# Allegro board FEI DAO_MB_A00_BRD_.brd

Outline 331.5 x 112.9 mm; copper layers: TOP, GND1, IN1, VCC, IN2, IN3, GND2, IN4, GND3, BOTTOM. Coordinates in mm from the lower left corner of the outline.

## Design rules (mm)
net group 5_10: nets PCH_SDVO_CTRLCLK PCH_SDVO_CTRLDATA
net group CARD_SMBCLK: nets CARD_SMBCLK CARD_SMBDAT
net group CLK_BUF_CKSSCD: nets CLK_BUF_CKSSCD CLK_BUF_CKSSCD#
net group CLK_BUF_DMI: nets CLK_BUF_DMI CLK_BUF_DMI#
net group CLK_BUF_DOT96: nets CLK_BUF_DOT96 CLK_BUF_DOT96#
net group CSS_1: nets CSSN_1 CSSP_1
net group DIFFPAIR0: nets HOST_DEBUG_RX HOST_DEBUG_TX
net group DMI_CRX_PTX_0: nets DMI_CRX_PTX_N0 DMI_CRX_PTX_P0
net group DMI_CRX_PTX_1: nets DMI_CRX_PTX_N1 DMI_CRX_PTX_P1
net group DMI_CRX_PTX_2: nets DMI_CRX_PTX_N2 DMI_CRX_PTX_P2
net group DMI_CRX_PTX_3: nets DMI_CRX_PTX_N3 DMI_CRX_PTX_P3
net group DMI_CTX_PRX_0: nets DMI_CTX_PRX_N0 DMI_CTX_PRX_P0
net group DMI_CTX_PRX_1: nets DMI_CTX_PRX_N1 DMI_CTX_PRX_P1
net group DMI_CTX_PRX_2: nets DMI_CTX_PRX_N2 DMI_CTX_PRX_P2
net group DMI_CTX_PRX_3: nets DMI_CTX_PRX_N3 DMI_CTX_PRX_P3
net group DMIC_CLK: nets DMIC0 DMIC_CLK
net group ESATA_PRX_DTX_P4_RP: nets ESATA_PRX_DTX_N4_RP ESATA_PRX_DTX_P4_RP
net group FDI_CTX_PRX_0: nets FDI_CTX_PRX_N0 FDI_CTX_PRX_P0
net group FDI_CTX_PRX_1: nets FDI_CTX_PRX_N1 FDI_CTX_PRX_P1
net group FDI_CTX_PRX_2: nets FDI_CTX_PRX_N2 FDI_CTX_PRX_P2
net group FDI_CTX_PRX_3: nets FDI_CTX_PRX_N3 FDI_CTX_PRX_P3
net group FDI_CTX_PRX_4: nets FDI_CTX_PRX_N4 FDI_CTX_PRX_P4
net group FDI_CTX_PRX_5: nets FDI_CTX_PRX_N5 FDI_CTX_PRX_P5
net group FDI_CTX_PRX_6: nets FDI_CTX_PRX_N6 FDI_CTX_PRX_P6
net group FDI_CTX_PRX_7: nets FDI_CTX_PRX_N7 FDI_CTX_PRX_P7
net group GND: nets GND GNDA
net group GPU_SMBCLK: nets GPU_SMBCLK GPU_SMBDAT
net group LCD_SMBCLK: nets LCD_SMBCLK LCD_SMBDAT
net group LDDC_DATA_PCH: nets LDDC_CLK_PCH LDDC_DATA_PCH
net group M_CLK_DDR0: nets M_CLK_DDR0 M_CLK_DDR#0
net group M_CLK_DDR1: nets M_CLK_DDR1 M_CLK_DDR#1
net group M_CLK_DDR2: nets M_CLK_DDR2 M_CLK_DDR#2
net group M_CLK_DDR3: nets M_CLK_DDR3 M_CLK_DDR#3
net group MSCLK: nets MSCLK MSDATA
net group NB_LAN_TX0: nets NB_LAN_TX0+ NB_LAN_TX0-
net group NB_LAN_TX1: nets NB_LAN_TX1+ NB_LAN_TX1-
net group NB_LAN_TX2: nets NB_LAN_TX2+ NB_LAN_TX2-
net group NB_LAN_TX3: nets NB_LAN_TX3+ NB_LAN_TX3-
net group PCH_CL_CLK1: nets PCH_CL_CLK1 PCH_CL_DATA1
net group PCH_CRT_DDC_CLK: nets PCH_CRT_DDC_CLK PCH_CRT_DDC_DAT
net group PCH_SDVO_CRTLCLK_R: nets PCH_SDVO_CTRLCLK_R PCH_SDVO_CTRLDATA_R
net group REM_DIODE1_4022: nets REM_DIODE1_N_4022 REM_DIODE1_P_4022
net group REM_DIODE2_4022: nets REM_DIODE2_N_4022 REM_DIODE2_P_4022
net group SATA_PRX_DTX_P4_B: nets SATA_PRX_DTX_N4_B SATA_PRX_DTX_P4_B
net group SATA_PTX_DRX_P4_B: nets SATA_PTX_DRX_N4_B SATA_PTX_DRX_P4_B
net group TMDSB_CON_CLK: nets TMDSB_CON_CLK TMDSB_CON_CLK#
net group TMDSB_PCH_CLK: nets TMDSB_PCH_CLK TMDSB_PCH_CLK#
net group TMDSB_PCH_CLK_C: nets TMDSB_PCH_CLK#_C TMDSB_PCH_CLK_C
net group TP_CLK: nets TP_CLK TP_DATA
net group UIM: nets UIM_CLK UIM_DATA
net group USB3RN1_D: nets USB3RN1_D- USB3RP1_D+
net group USB3RN2_D: nets USB3RN2_D- USB3RP2_D+
net group USB3RN3_D: nets USB3RN3_D- USB3RP3_D+
net group USB3TN1_D: nets USB3TN1_D- USB3TP1_D+
net group USB3TP2_D: nets USB3TN2_D- USB3TP2_D+
net group USB3TP3_D: nets USB3TN3_D- USB3TP3_D+
net group USBP13: nets USBP13+ USBP13-
net group USBP13_R_D: nets USBP13_R_D+ USBP13_R_D-
net group USH_SMBCLK: nets USH_SMBCLK USH_SMBDAT
net group ASYNCHRONOUS: nets EDP_COMP PEG_COMP SATA3_COMP SATA_COMP
net group AUDIO: nets AUD_HP_OUT_L AUD_HP_OUT_L1 AUD_HP_OUT_L2 AUD_HP_OUT_R AUD_HP_OUT_R1 AUD_HP_OUT_R2 EXT_MIC INT_SPK_L+ INT_SPK_L- INT_SPK_R+ INT_SPK_R- INT_SPKL_L+ INT_SPKR_L- INT_SPKR_R+ INT_SPKR_R- ME_FWP MIC_IN_L MIC_IN_R PCH_AZ_BITCLK PCH_AZ_CODEC_BITCLK PCH_AZ_CODEC_RST# PCH_AZ_CODEC_SDIN0 PCH_AZ_CODEC_SDOUT PCH_AZ_CODEC_SYNC PCH_AZ_RST# PCH_AZ_SDIN0_R PCH_AZ_SDOUT PCH_AZ_SYNC PCH_AZ_SYNC_Q
net group CARD READER: nets SD/MMCCD# SD/MMCDAT0 SD/MMCDAT0_R SD/MMCDAT1 SD/MMCDAT1_R SD/MMCDAT2 SD/MMCDAT2_R SD/MMCDAT3 SD/MMCDAT3_R SD/MMCDAT4 SD/MMCDAT4_R SD/MMCDAT5 SD/MMCDAT5_R SD/MMCDAT6 SD/MMCDAT6_R SD/MMCDAT7 SD/MMCDAT7_R
net group CPU SIDEBAND: nets DDR3_DRAMRST# DDR3_DRAMRST#_CPU DDR3_DRAMRST#_R H_CPUPWRGD H_CPUPWRGD_XDP H_PM_SYNC H_PROCHOT# H_PROCHOT#_R H_THERMTRIP# H_THERMTRIP#_R PCH_PLTRST# PCH_PLTRST#_BUF PCH_PLTRST#_EC PCH_PLTRST#_R PM_DRAM_PWRGD PM_DRAM_PWRGD_CPU PROCHOT#_EC RUNPWROK_AND THERMATRIP2# VCCPWRGOOD_0_R XDP_RST#_R
net group CRT: nets B G HSYNC HSYNC_BUF HSYNC_CRT JVGA_HS JVGA_VS R VSYNC VSYNC_BUF VSYNC_CRT
net group CRT_20: nets BLUE_CRT GREEN_CRT RED_CRT
net group DDR_A_CMD: nets DDR_A_BS0 DDR_A_BS1 DDR_A_BS2 DDR_A_CAS# DDR_A_MA0 DDR_A_MA1 DDR_A_MA2 DDR_A_MA3 DDR_A_MA4 DDR_A_MA5 DDR_A_MA6 DDR_A_MA7 DDR_A_MA8 DDR_A_MA9 DDR_A_MA10 DDR_A_MA11 DDR_A_MA12 DDR_A_MA13 DDR_A_MA14 DDR_A_MA15 DDR_A_RAS# DDR_A_WE#
net group DDR_A_CTL: nets DDR_CKE0_DIMMA DDR_CKE1_DIMMA DDR_CS0_DIMMA# DDR_CS1_DIMMA#
net group DDR_A_D0: nets DDR_A_D0 DDR_A_D1 DDR_A_D2 DDR_A_D3 DDR_A_D4 DDR_A_D5 DDR_A_D6 DDR_A_D7
net group DDR_A_D1: nets DDR_A_D8 DDR_A_D9 DDR_A_D10 DDR_A_D11 DDR_A_D12 DDR_A_D13 DDR_A_D14 DDR_A_D15
net group DDR_A_D2: nets DDR_A_D16 DDR_A_D17 DDR_A_D18 DDR_A_D19 DDR_A_D20 DDR_A_D21 DDR_A_D22 DDR_A_D23
net group DDR_A_D3: nets DDR_A_D24 DDR_A_D25 DDR_A_D26 DDR_A_D27 DDR_A_D28 DDR_A_D29 DDR_A_D30 DDR_A_D31
net group DDR_A_D4: nets DDR_A_D32 DDR_A_D33 DDR_A_D34 DDR_A_D35 DDR_A_D36 DDR_A_D37 DDR_A_D38 DDR_A_D39
net group DDR_A_D5: nets DDR_A_D40 DDR_A_D41 DDR_A_D42 DDR_A_D43 DDR_A_D44 DDR_A_D45 DDR_A_D46 DDR_A_D47
net group DDR_A_D6: nets DDR_A_D48 DDR_A_D49 DDR_A_D50 DDR_A_D51 DDR_A_D52 DDR_A_D53 DDR_A_D54 DDR_A_D55
net group DDR_A_D7: nets DDR_A_D56 DDR_A_D57 DDR_A_D58 DDR_A_D59 DDR_A_D60 DDR_A_D61 DDR_A_D62 DDR_A_D63
net group DDR_A_DQS: nets DDR_A_DQS0 DDR_A_DQS1 DDR_A_DQS2 DDR_A_DQS3 DDR_A_DQS4 DDR_A_DQS5 DDR_A_DQS6 DDR_A_DQS7 DDR_A_DQS#0 DDR_A_DQS#1 DDR_A_DQS#2 DDR_A_DQS#3 DDR_A_DQS#4 DDR_A_DQS#5 DDR_A_DQS#6 DDR_A_DQS#7
net group DDR_B_CMD: nets DDR_B_BS0 DDR_B_BS1 DDR_B_BS2 DDR_B_CAS# DDR_B_MA0 DDR_B_MA1 DDR_B_MA2 DDR_B_MA3 DDR_B_MA4 DDR_B_MA5 DDR_B_MA6 DDR_B_MA7 DDR_B_MA8 DDR_B_MA9 DDR_B_MA10 DDR_B_MA11 DDR_B_MA12 DDR_B_MA13 DDR_B_MA14 DDR_B_MA15 DDR_B_RAS# DDR_B_WE#
net group DDR_B_CTL: nets DDR_CKE2_DIMMB DDR_CKE3_DIMMB DDR_CS2_DIMMB# DDR_CS3_DIMMB# M_ODT0 M_ODT1 M_ODT2 M_ODT3
net group DDR_B_D0: nets DDR_B_D0 DDR_B_D1 DDR_B_D2 DDR_B_D3 DDR_B_D4 DDR_B_D5 DDR_B_D6 DDR_B_D7
net group DDR_B_D1: nets DDR_B_D8 DDR_B_D9 DDR_B_D10 DDR_B_D11 DDR_B_D12 DDR_B_D13 DDR_B_D14 DDR_B_D15
net group DDR_B_D2: nets DDR_B_D16 DDR_B_D17 DDR_B_D18 DDR_B_D19 DDR_B_D20 DDR_B_D21 DDR_B_D22 DDR_B_D23
net group DDR_B_D3: nets DDR_B_D24 DDR_B_D25 DDR_B_D26 DDR_B_D27 DDR_B_D28 DDR_B_D29 DDR_B_D30 DDR_B_D31
net group DDR_B_D4: nets DDR_B_D32 DDR_B_D33 DDR_B_D34 DDR_B_D35 DDR_B_D36 DDR_B_D37 DDR_B_D38 DDR_B_D39
net group DDR_B_D5: nets DDR_B_D40 DDR_B_D41 DDR_B_D42 DDR_B_D43 DDR_B_D44 DDR_B_D45 DDR_B_D46 DDR_B_D47
net group DDR_B_D6: nets DDR_B_D48 DDR_B_D49 DDR_B_D50 DDR_B_D51 DDR_B_D52 DDR_B_D53 DDR_B_D54 DDR_B_D55
net group DDR_B_D7: nets DDR_B_D56 DDR_B_D57 DDR_B_D58 DDR_B_D59 DDR_B_D60 DDR_B_D61 DDR_B_D62 DDR_B_D63
net group DDR_B_DQS: nets DDR_B_DQS0 DDR_B_DQS1 DDR_B_DQS2 DDR_B_DQS3 DDR_B_DQS4 DDR_B_DQS5 DDR_B_DQS6 DDR_B_DQS7 DDR_B_DQS#0 DDR_B_DQS#1 DDR_B_DQS#2 DDR_B_DQS#3 DDR_B_DQS#4 DDR_B_DQS#5 DDR_B_DQS#6 DDR_B_DQS#7
net group FDI_SYN: nets FDI_FSYNC0 FDI_FSYNC1 FDI_INT FDI_LSYNC0 FDI_LSYNC1
net group HDMI: nets TMDSB_CON_N0 TMDSB_CON_N1 TMDSB_CON_N2 TMDSB_CON_P0 TMDSB_CON_P1 TMDSB_CON_P2 TMDSB_PCH_N0 TMDSB_PCH_N0_C TMDSB_PCH_N1 TMDSB_PCH_N1_C TMDSB_PCH_N2 TMDSB_PCH_N2_C TMDSB_PCH_P0 TMDSB_PCH_P0_C TMDSB_PCH_P1 TMDSB_PCH_P1_C TMDSB_PCH_P2 TMDSB_PCH_P2_C
net group LAN: nets LAN_TX0+ LAN_TX0+_L LAN_TX0+_R LAN_TX0- LAN_TX0-_L LAN_TX0-_R LAN_TX1+ LAN_TX1+_L LAN_TX1+_R LAN_TX1- LAN_TX1-_L LAN_TX1-_R LAN_TX2+ LAN_TX2+_L LAN_TX2+_R LAN_TX2- LAN_TX2-_L LAN_TX2-_R LAN_TX3+ LAN_TX3+_L LAN_TX3+_R LAN_TX3- LAN_TX3-_L LAN_TX3-_R
net group LVDS: nets LCD_A0+_PCH LCD_A0-_PCH LCD_A1+_PCH LCD_A1-_PCH LCD_A2+_PCH LCD_A2-_PCH LCD_ACLK+_PCH LCD_ACLK-_PCH LCD_B0+_PCH LCD_B0-_PCH LCD_B1+_PCH LCD_B1-_PCH LCD_B2+_PCH LCD_B2-_PCH LCD_BCLK+_PCH LCD_BCLK-_PCH
net group PCIE: nets PCIE_MCARD1_DET# PCIE_MCARD2_DET# PCIE_MCARD2_DET#_R PCIE_PRX_GLANTX_N7 PCIE_PRX_GLANTX_N7_C PCIE_PRX_GLANTX_P7 PCIE_PRX_GLANTX_P7_C PCIE_PRX_MMITX_N6 PCIE_PRX_MMITX_N6_C PCIE_PRX_MMITX_P6 PCIE_PRX_MMITX_P6_C PCIE_PRX_WANTX_N1 PCIE_PRX_WANTX_P1 PCIE_PRX_WLANTX_N2 PCIE_PRX_WLANTX_P2 PCIE_PTX_GLANRX_N7 PCIE_PTX_GLANRX_N7_C PCIE_PTX_GLANRX_P7 PCIE_PTX_GLANRX_P7_C PCIE_PTX_MMIRX_N6 PCIE_PTX_MMIRX_N6_C PCIE_PTX_MMIRX_P6 PCIE_PTX_MMIRX_P6_C PCIE_PTX_WANRX_N1 PCIE_PTX_WANRX_N1_C PCIE_PTX_WANRX_P1 PCIE_PTX_WANRX_P1_C PCIE_PTX_WLANRX_N2 PCIE_PTX_WLANRX_N2_C PCIE_PTX_WLANRX_P2 PCIE_PTX_WLANRX_P2_C
net group PLAT CLK: nets CLK_CPU_DMI CLK_CPU_DMI# CLK_CPU_ITP CLK_CPU_ITP# CLK_PCIE_LAN CLK_PCIE_LAN# CLK_PCIE_MINI1 CLK_PCIE_MINI1# CLK_PCIE_MINI2 CLK_PCIE_MINI2# CLK_PCIE_MMI CLK_PCIE_MMI# CLK_XDP CLK_XDP# CLK_XDP_ITP CLK_XDP_ITP# CPU_DPLL CPU_DPLL#
net group RTC: nets PCH_RTCRST# PCH_RTCX1 PCH_RTCX2 PCH_RTCX2_R SRTCRST#
net group SATA: nets ESATA_PRX_DTX_N4_C ESATA_PRX_DTX_P4_C ESATA_PTX_DRX_N4_C ESATA_PTX_DRX_N4_RP ESATA_PTX_DRX_P4_C ESATA_PTX_DRX_P4_RP MSATA_PRX_DTX_N0 MSATA_PRX_DTX_N0_C MSATA_PRX_DTX_P0 MSATA_PRX_DTX_P0_C MSATA_PTX_DRX_N0 MSATA_PTX_DRX_N0_C MSATA_PTX_DRX_P0 MSATA_PTX_DRX_P0_C SATA_PRX_DTX_N4 SATA_PRX_DTX_P4 SATA_PTX_DRX_N4 SATA_PTX_DRX_P4
net group SENSE: nets VCC_AXG_SENSE VCCSENSE VCCSENSE_R VSS_AXG_SENSE VSSSENSE VSSSENSE_R
net group SMB: nets BAY_SMBCLK BAY_SMBDAT CHARGER_SMBCLK CHARGER_SMBDAT DDR_XDP_WAN_SMBCLK DDR_XDP_WAN_SMBDAT LAN_SMBCLK LAN_SMBCLK_R LAN_SMBDATA LAN_SMBDATA_R MEM_SMBCLK MEM_SMBDATA PBAT_SMBCLK PBAT_SMBDAT SML1_SMBCLK SML1_SMBDATA WWAN_SMBCLK WWAN_SMBDAT
net group SPI: nets SPI_CLK32 SPI_CLK64 SPI_CLK_TAA SPI_DIN32 SPI_DIN64 SPI_DIN_TAA SPI_DO32 SPI_DO64 SPI_DO_TAA SPI_HOLD# SPI_WP#_SEL SPI_WP#_SEL_R
net group SVID: nets H_CPU_SVIDALRT# PECI_EC PECI_EC_R VIDALERT_N VIDSCLK VIDSOUT
net group USB: nets USBP0+ USBP0- USBP0_D+ USBP0_D- USBP0_R_D+ USBP0_R_D- USBP1+ USBP1- USBP1_R_D+ USBP1_R_D- USBP2+ USBP2- USBP2_D+ USBP2_D- USBP4+ USBP4- USBP5+ USBP5- USBP7+ USBP7- USBP11+ USBP11- USBP12+ USBP12- USBP12_D+ USBP12_D-
net group USB3: nets USB3RN1 USB3RN2 USB3RN3 USB3RP1 USB3RP2 USB3RP3 USB3T_N2 USB3T_N3 USB3T_P2 USB3T_P3 USB3TN1 USB3TN1_C USB3TN2 USB3TN3 USB3TP1 USB3TP1_C USB3TP2 USB3TP3
nets with their own width: min track width 0.127; nets AUD_SENSE_A
nets with their own width: min track width 0.254; nets +1.05V_MP BATT_WHITE BATT_YELLOW BREATH_LED#_Q N25856953 SATA_LED WLAN_LED
nets with their own width: min track width 0.508; nets +3.3V_PCIE_WWAN +3.3V_RUN +DIMM1_VREF_DQ +V_DDR_REF +V_DDR_SMREF GND_CHASSIS N50370296 N50384913 N50388248 N50391897 REGCTL_PNP10 SM_RCOMP2 Z2805 Z2806 Z2807 Z2808
nets with their own width: min track width 0.762; nets +1.8V_RUN_LVDS
nets with their own width: min track width 1.016; nets +0.75V_DDR_VTT +1.5V_RUN +3.3V_LAN +3.3V_PCIE_FLASH +3.3V_RUN_CARD +3.3V_RUN_TPM +5V_ALW +CAMERA_VDD +CRT_VCC +VDISPLAY_VCC
nets with their own width: min track width 1.524; nets +3.3V_RUN_DVDD +3.3V_WLAN +3.3VDDH +5V_USB_PWR +PE_VDDH +VDDA_AVDD +VDDA_PVDD
nets with their own width: min track width 2.032; nets +3.3V_ALW_PCH +5V_USB_CHG_PWR +BL_PWR_SRC +DIMM2_VREF_DQ +LCDVDD +PWR_SRC +SATA_SIDE_PWR

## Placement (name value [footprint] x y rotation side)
C36  -  [C_0603NEW]  303.81 78.42 0 top
C37  -  [C_0603NEW]  303.81 79.69 0 top
C38  -  [C_0603NEW]  303.81 82.29 0 top
C39  -  [C_0603NEW]  303.81 83.56 0 top
C44  -  [C_0402NEW]  257.26 49.88 270 bottom
C45  -  [C_0402NEW]  258.15 49.88 270 bottom
C219  -  [C_0805NEW]  167.23 98.7 0 bottom
C243  -  [C_0402NEW]  134.36 104.34 270 bottom
C246  -  [C_0603NEW]  140.81 103.06 270 bottom
C266  -  [C_0402NEW]  122.45 55.39 0 top
C270  -  [C_0402NEW]  156.77 98.31 0 bottom
C271  -  [C_0402NEW]  154.36 99.93 315 bottom
C272  -  [C_0402NEW]  64.6 39.18 270 top
C273  -  [C_0402NEW]  156.95 107.3 90 bottom
C274  -  [C_0402NEW]  164.89 100.01 0 bottom
C277  -  [C_0402NEW]  128.17 81.73 90 bottom
C278  -  [C_0402NEW]  168.85 96.14 0 bottom
C282  -  [C_0402NEW]  154.82 102.68 180 bottom
C288  -  [C_0402NEW]  185.35 29.07 90 bottom
C289  -  [C_0402NEW]  188.44 32.46 90 bottom
C292  -  [C_0402NEW]  134.36 101.6 90 bottom
C293  -  [C_0402NEW]  136.17 103.43 180 bottom
C296  -  [C_0603NEW]  140.9 100.45 270 bottom
C297  -  [C_0402NEW]  143.69 98.61 0 bottom
C298  -  [C_0402NEW]  107 88.97 180 bottom
C299  -  [C_0402NEW]  149.75 109.38 180 bottom
C300  -  [C_0603NEW]  150.27 106.73 180 bottom
C301  -  [C_0402NEW]  132.85 107.57 0 bottom
C302  -  [C_0402NEW]  108.17 106.74 270 top
C337  -  [C_0402NEW]  80.33 99.76 0 bottom
C338  -  [C_0805NEW]  79.39 98.43 0 bottom
C346  -  [C_0402NEW]  68.31 93.07 270 bottom
C347  -  [C_0402NEW]  69.2 93.07 270 bottom
C348  -  [C_0402NEW]  65.45 95.3 270 bottom
C349  -  [C_0402NEW]  66.34 95.3 270 bottom
C350  -  [C_0402NEW]  76.19 95.68 270 bottom
C351  -  [C_0402NEW]  77.07 95.68 270 bottom
C352  -  [C_0402NEW]  72.3 95.68 270 bottom
C353  -  [C_0402NEW]  73.19 95.68 270 bottom
C412  -  [C_0402NEW]  306.9 55.97 180 bottom
C413  -  [C_0402NEW]  306.9 55.08 180 bottom
C458  -  [C_0402NEW]  281.46 83.75 180 top
C459  -  [C_0402NEW]  281.46 82.86 180 top
C460  -  [C_0402NEW]  280.56 81.93 0 top
C461  -  [C_0402NEW]  280.56 81.04 0 top
C462  -  [C_0603NEW]  294.44 84.39 90 top
C463  -  [C_0402NEW]  287.32 75.78 0 top
C464  -  [C_0603NEW]  293.02 81.62 0 top
C466  -  [C_0402NEW]  281.46 80.12 180 top
C467  -  [C_0402NEW]  281.46 84.69 180 top
C468  -  [C_0402NEW]  293.44 79.83 0 top
C469  -  [C_0402NEW]  291.58 83.46 90 top
C470  -  [C_0402NEW]  292.5 75.73 90 top
C471  -  [C_0402NEW]  292.5 78.42 270 top
C475  -  [C_0603NEW]  314.32 43.87 270 bottom
C476  -  [C_0402NEW]  314.32 46.08 90 bottom
C477  -  [C_0402NEW]  308.73 46.08 90 bottom
C478  -  [C_0402NEW]  295.1 88.21 270 top
C550  -  [C_0402NEW]  270.4 49.11 0 bottom
C551  -  [C_0402NEW]  270.41 53.34 90 bottom
C552  -  [C_0402NEW]  271.3 53.35 90 bottom
C553  -  [C_0402NEW]  258.16 53.49 180 bottom
C554  -  [C_0402NEW]  258.18 55.5 180 bottom
C559  -  [C_0402NEW]  279.28 8.83 270 top
C560  -  [C_0603NEW]  280.36 8.81 270 top
C561  -  [C_0603NEW]  277.31 8.81 270 top
C562  -  [C_0402NEW]  278.39 8.83 270 top
C563  -  [C_0402NEW]  275.86 11.1 180 top
C564  -  [C_0603NEW]  276.13 10.04 180 top
C565  -  [C_0402NEW]  285.93 10.97 0 top
C566  -  [C_0603NEW]  285.69 9.89 0 top
C567  -  [C_0402NEW]  274.93 13.94 0 top
C568  -  [C_0402NEW]  274.93 14.83 0 top
C569  -  [C_0402NEW]  274.95 13 0 top
C571  -  [C_0402NEW]  274.95 12.11 0 top
C572  -  [C_0603NEW]  294.8 16.6 0 top
C573  -  [C_0402NEW]  278.39 18.45 90 top
C574  -  [C_0402NEW]  277.5 18.45 90 top
C575  -  [C_0402NEW]  283.67 8.83 270 top
C576  -  [C_0402NEW]  284.56 8.83 270 top
C577  -  [C_0603NEW]  285.69 8.62 0 top
C578  -  [C_0603NEW]  276.42 18.46 90 top
C579  -  [C_0402NEW]  281.9 8.83 270 top
C593  -  [C_0402NEW]  278.63 42.46 90 top
C594  -  [C_0402NEW]  298.42 42.36 90 top
C595  -  [C_0402NEW]  258.13 64.87 270 top
C596  -  [C_0402NEW]  251.79 53.74 90 bottom
C597  -  [C_0402NEW]  284.66 30.91 90 bottom
C598  -  [C_0402NEW]  250.9 53.74 90 bottom
C599  -  [C_0402NEW]  283.77 30.91 90 bottom
C600  -  [C_0402NEW]  270.74 64.89 0 bottom
C601  -  [C_0402NEW]  251.97 66.22 0 top
C602  -  [C_0402NEW]  270.74 68.19 0 bottom
C603  -  [C_0402NEW]  239.74 67.07 270 top
C604  -  [C_0402NEW]  246.31 56.12 270 bottom
C605  -  [C_0402NEW]  270.74 66.29 0 bottom
C606  -  [C_0402NEW]  240.63 66.15 90 top
C607  -  [C_0402NEW]  271.66 67.24 180 bottom
C608  -  [C_0603NEW]  247.44 56.02 270 bottom
C609  -  [C_0402NEW]  238.82 67.05 270 top
C610  -  [C_0402NEW]  299.43 42.36 90 top
C611  -  [C_0402NEW]  287.46 43.32 270 top
C612  -  [C_0402NEW]  276.22 43.32 270 top
C613  -  [C_0805NEW]  279.52 31.62 270 bottom
C614  -  [C_0402NEW]  280.92 31.82 270 bottom
C615  -  [C_D2E]  306.55 35.33 90 bottom
C616  -  [C_0402NEW]  292.27 30.22 0 bottom
C617  -  [C_0402NEW]  271.23 26.49 180 bottom
C618  -  [C_0402NEW]  271.23 25.6 180 bottom
C619  -  [C_0402NEW]  259.86 39.77 0 top
C620  -  [C_0402NEW]  259.92 27.77 0 top
C621  -  [C_0402NEW]  259.86 29.55 0 top
C622  -  [C_0402NEW]  259.86 41.42 0 top
C623  -  [C_0402NEW]  259.86 28.66 0 top
C624  -  [C_0402NEW]  265.91 20.96 90 top
C625  -  [C_0402NEW]  265.02 20.96 90 top
C626  -  [C_0603NEW]  263.94 21.8 270 top
C627  -  [C_0402NEW]  259.75 23.12 90 top
C628  -  [C_0402NEW]  286.71 31.17 180 bottom
C629  -  [C_0402NEW]  286.69 29.26 90 bottom
C630  -  [C_0402NEW]  292.27 29.21 0 bottom
C631  -  [C_0402NEW]  292.27 31.17 0 bottom
C632  -  [C_0402NEW]  240.63 56 0 bottom
C644  -  [C_0402NEW]  315.26 38.19 90 top
C650  -  [C_0402NEW]  241.85 47.62 0 bottom
C651  -  [C_B2]  313.19 52.24 90 bottom
C654  -  [C_0402NEW]  313.82 54.75 90 bottom
C661  -  [C_0402NEW]  243.33 74.87 0 top
C662  -  [C_0402NEW]  237.28 80.76 90 top
C663  -  [C_0402NEW]  238.24 73.62 270 top
C664  -  [C_0402NEW]  239.13 73.62 270 top
C665  -  [C_0402NEW]  240.02 73.62 270 top
C666  -  [C_0402NEW]  240.91 73.62 270 top
C675  -  [C_0402NEW]  18.93 43.34 180 bottom
C676  -  [C_0805NEW]  20.38 43.29 0 bottom
C705  -  [C_0603NEW]  270.78 66.55 0 top
C706  -  [C_0402NEW]  271.84 77.39 0 top
C707  -  [C_0402NEW]  270.78 67.97 0 top
C708  -  [C_0402NEW]  261.38 66.91 90 top
C709  -  [C_0402NEW]  262.41 83.1 90 top
C710  -  [C_0402NEW]  256.23 76.51 180 top
C712  -  [C_0402NEW]  274.11 79.22 0 top
C713  -  [C_0402NEW]  275.99 78.24 0 top
C714  -  [C_0603NEW]  257.36 82.86 90 top
C715  -  [C_0402NEW]  303.95 60.32 0 bottom
C716  -  [C_0402NEW]  255.97 81.21 180 top
C720  -  [C_0402NEW]  140.23 24.09 0 bottom
C721  -  [C_0402NEW]  299.53 50.41 180 top
C722  -  [C_0402NEW]  299.51 48.54 180 top
C723  -  [C_0402NEW]  294.3 49.4 0 top
C725  -  [C_0402NEW]  289.36 66.21 90 top
C726  -  [C_0402NEW]  286.63 66.21 90 top
C727  -  [C_0402NEW]  295.83 55.18 0 top
C728  -  [C_0402NEW]  295.83 59.62 0 top
C729  -  [C_0402NEW]  289.04 50.3 270 top
C730  -  [C_0603NEW]  280.6 64.96 180 top
C731  -  [C_0402NEW]  285.23 50.24 270 top
C732  -  [C_0402NEW]  280.36 63.81 180 top
C735  -  [C_0402NEW]  285.23 47.04 90 top
C737  -  [C_0402NEW]  280.36 53.72 180 top
C739  -  [C_0402NEW]  280.36 57.4 180 top
C740  -  [C_0603NEW]  298.29 61.68 0 top
C741  -  [C_0402NEW]  292.49 49.34 180 top
C742  -  [C_0402NEW]  296.74 58.61 180 top
C743  -  [C_0402NEW]  290 49.39 90 top
C744  -  [C_0402NEW]  299.47 59.62 180 top
C745  -  [C_0402NEW]  208.37 13.84 0 bottom
C746  -  [C_0402NEW]  212.24 38.78 180 bottom
C747  -  [C_0402NEW]  285.74 68.46 90 top
C749  -  [C_0402NEW]  220.46 29.6 90 top
C750  -  [C_0402NEW]  220.46 28.76 270 top
C751  -  [C_0402NEW]  222.34 31.32 90 top
C752  -  [C_0402NEW]  224.12 31.32 90 top
C755  -  [C_0402NEW]  214.1 8.91 180 top
C756  -  [C_0402NEW]  221.63 26.63 0 top
C758  -  [C_0402NEW]  223.86 26.63 0 top
C759  -  [C_0402NEW]  308.7 45.92 90 top
C760  -  [C_0603NEW]  200.37 9.28 180 top
C761  -  [C_0805NEW]  186.04 9.93 180 bottom
C762  -  [C_0402NEW]  206.46 5.99 0 bottom
C763  -  [C_0402NEW]  189.53 17.03 90 top
C764  -  [C_0805NEW]  226.85 49.92 90 bottom
C765  -  [C_0402NEW]  214.1 9.87 180 top
C766  -  [C_0402NEW]  230.28 52.65 90 bottom
C767  -  [C_0402NEW]  189.38 17.64 0 bottom
C768  -  [C_0603NEW]  167.16 83.84 0 bottom
C769  -  [C_0603NEW]  191.45 8.54 90 bottom
C770  -  [C_0402NEW]  166.27 78.08 270 bottom
C771  -  [C_0402NEW]  189.26 3.78 270 bottom
C772  -  [C_0603NEW]  139.16 40.54 0 bottom
C773  -  [C_0402NEW]  136.06 45.81 180 bottom
C774  -  [C_0402NEW]  188.56 12.74 180 top
C775  -  [C_0402NEW]  52.27 10.69 90 top
C776  -  [C_0402NEW]  71.43 92.06 90 bottom
C777  -  [C_0402NEW]  271.35 58.46 270 top
C778  -  [C_0402NEW]  258.11 85.24 180 top
C779  -  [C_0402NEW]  286.15 41.46 270 top
C780  -  [C_0402NEW]  283.15 19.14 90 top
C781  -  [C_0402NEW]  203.31 16.48 180 top
C782  -  [C_0402NEW]  252.98 18.72 90 top
C783  -  [C_0402NEW]  131.56 109.42 180 bottom
C784  -  [C_0402NEW]  165.87 45.97 270 top
C785  -  [C_0402NEW]  228.42 16.08 90 top
C786  -  [C_0402NEW]  44 71.63 180 top
C787  -  [C_0402NEW]  70.3 97.11 90 bottom
C952  -  [C_0603NEW]  38.18 39.51 90 top
C953  -  [C_0402NEW]  37.98 38.51 0 top
C954  -  [C_0603NEW]  37.42 32.03 0 top
C955  -  [C_0603NEW]  27.29 31.37 270 top
C956  -  [C_0603NEW]  24.92 30.44 270 top
C957  -  [C_0402NEW]  28.53 31.09 270 top
C958  -  [C_0603NEW]  39.78 29.6 0 top
C959  -  [C_0402NEW]  29.44 28.53 180 top
C960  -  [C_0603NEW]  35.78 31.21 270 top
C961  -  [C_0402NEW]  33.75 31.09 270 top
C962  -  [C_0603NEW]  25.43 34 180 top
C963  -  [C_0603NEW]  25.43 32.73 180 top
C964  -  [C_0603NEW]  25.42 35.5 180 top
C965  -  [C_0603NEW]  28.72 43.51 90 top
C966  -  [C_0603NEW]  31.83 43.38 180 top
C967  -  [C_0402NEW]  37.17 45.61 270 top
C973  -  [C_0402NEW]  32.29 29.31 270 top
C974  -  [C_0402NEW]  33.24 29.31 270 top
C975  -  [C_0402NEW]  31.34 29.31 270 top
C976  -  [C_0402NEW]  30.38 29.31 270 top
C977  -  [C_0402NEW]  39.76 36.68 0 top
C978  -  [C_0402NEW]  39.76 35.8 0 top
C979  -  [C_0402NEW]  33.46 43.79 0 top
C980  -  [C_0402NEW]  36.62 42.89 180 top
C981  -  [C_0402NEW]  16.35 39.63 90 top
C982  -  [C_0402NEW]  17.63 28.85 270 bottom
C983  -  [C_0402NEW]  18.38 28.86 270 top
C994  -  [C_0402NEW]  37.98 34.88 0 top
C1104  -  [C_1808]  309.67 68.11 0 bottom
C1105  -  [C_0402NEW]  38.89 42.79 180 top
C1106  -  [C_0402NEW]  38.89 41.91 180 top
C1163  -  [C_0603NEW]  25.37 40.6 180 top
C1167  -  [C_0402NEW]  315.38 46.03 0 bottom
C1168  -  [C_0402NEW]  314.76 90.37 0 top
C1169  -  [C_0603NEW]  314.51 89.24 0 top
C1177  -  [C_0805NEW]  295.93 84.39 90 top
C1178  -  [C_0805NEW]  277.89 80.5 90 top
C1179  -  [C_0402NEW]  157.9 107.3 90 bottom
C1180  -  [C_0603NEW]  27.45 43.51 90 top
C1201  -  [C_0402NEW]  11.04 76.69 90 top
C1202  -  [C_0402NEW]  9.9 67.95 270 bottom
C1203  -  [C_0402NEW]  11.63 71.42 90 top
C1204  -  [C_0402NEW]  11.63 74.21 270 top
C1205  -  [C_0402NEW]  10.15 71.15 90 bottom
C1206  -  [C_0402NEW]  10.15 72.99 90 bottom
C1207  -  [C_0402NEW]  10.15 75.78 270 bottom
C1208  -  [C_0402NEW]  10 80.79 90 top
C1209  -  [C_0402NEW]  10.15 79.38 270 bottom
C1210  -  [C_0402NEW]  10.15 76.69 90 bottom
C1211  -  [C_0402NEW]  19.23 36.71 270 bottom
C1212  -  [C_0402NEW]  19.23 34.02 90 bottom
C1213  -  [C_0402NEW]  19.23 32.18 90 bottom
C1216  -  [C_0402NEW]  74.26 98.59 270 bottom
C1217  -  [C_0402NEW]  71.21 98.6 270 bottom
C1218  -  [C_0402NEW]  75.13 98.59 270 bottom
C1219  -  [C_0402NEW]  78.15 98.57 270 bottom
C1220  -  [C_0402NEW]  68.95 100.07 0 bottom
C1221  -  [C_0402NEW]  68.95 98.89 0 bottom
C1222  -  [C_0402NEW]  64.6 99.76 90 bottom
C1223  -  [C_0402NEW]  66.02 99.78 90 bottom
C1224  -  [C_0402NEW]  23.22 78.83 180 top
C1225  -  [C_0402NEW]  10.15 77.61 270 top
C1230  -  [C_0805NEW]  304.54 50.61 270 bottom
C1231  -  [C_0402NEW]  304.51 52.08 90 bottom
C1232  -  [C_B2]  243.47 93.75 0 bottom
C1233  -  [C_0402NEW]  264.24 95.08 0 bottom
C1234  -  [C_0402NEW]  261 91.6 270 bottom
C1235  -  [C_0402NEW]  261.89 91.6 270 bottom
C1236  -  [C_0402NEW]  252.02 94.15 90 bottom
C1237  -  [C_0402NEW]  252.98 94.15 90 bottom
C1238  -  [C_0402NEW]  260.28 94.15 90 bottom
C1239  -  [C_0402NEW]  261.17 94.15 90 bottom
C1242  -  [C_0402NEW]  25.67 51.63 0 bottom
C1243  -  [C_0402NEW]  25.67 50.75 0 bottom
C1244  -  [C_0402NEW]  18.12 53.62 90 top
C1245  -  [C_B2]  18.57 53.96 270 bottom
C1246  -  [C_0402NEW]  145 50.58 270 top
C1247  -  [C_0402NEW]  287.03 24.42 0 top
C1248  -  [C_0402NEW]  269.52 12.2 0 bottom
C1249  -  [C_0402NEW]  271.32 61.44 270 top
C1278  -  [C_0402NEW]  87.41 12.27 90 bottom
C1279  -  [C_0402NEW]  84.55 12.27 90 bottom
C1304  -  [C_0402NEW]  238 26.93 180 top
C1305  -  [C_0402NEW]  314.36 24.76 180 top
C1306  -  [C_0402NEW]  314.36 22.92 180 top
C1307  -  [C_0402NEW]  314.36 22.03 180 top
C1308  -  [C_0402NEW]  33.93 12.85 0 bottom
C1309  -  [C_0402NEW]  271.96 28.85 180 bottom
C1310  -  [C_0402NEW]  271.96 29.74 180 bottom
C1311  -  [C_0402NEW]  149.75 108.48 180 bottom
C1316  -  [C_0402NEW]  146.07 53.12 270 top
C1317  -  [C_0402NEW]  146.94 53.4 270 top
C1318  -  [C_0402NEW]  243.72 59.62 0 top
C1319  -  [C_0402NEW]  246.4 59.62 180 top
C1320  -  [C_0402NEW]  247.67 59.64 0 top
C1321  -  [C_0402NEW]  250.34 59.64 180 top
C1322  -  [C_0402NEW]  218.43 2.36 180 bottom
C1323  -  [C_0402NEW]  290.14 87.6 270 top
C1324  -  [C_0402NEW]  298.89 68.4 90 top
C1325  -  [C_0402NEW]  297.93 68.4 90 top
C1326  -  [C_0402NEW]  301.97 86.88 270 top
C1327  -  [C_0402NEW]  302.16 81.8 180 top
C1328  -  [C_0402NEW]  301.82 78.95 180 top
C1329  -  [C_0402NEW]  301.52 77.63 270 top
C1330  -  [C_0402NEW]  107 88.06 180 bottom
C1331  -  [C_0402NEW]  132.84 106.61 0 bottom
C1332  -  [C_0402NEW]  107.13 90.78 270 bottom
C1333  -  [C_0402NEW]  104.46 90.77 270 bottom
CC65  -  [C_0402NEW]  92.87 82.94 0 top
CC135  -  [C_0603NEW]  98.29 18.16 270 bottom
CC136  -  [C_0402NEW]  104.45 10.74 0 top
CC140  -  [C_0402NEW]  139.11 70.32 180 bottom
CC141  -  [C_0402NEW]  128.43 68.04 180 top
CC149  -  [C_0402NEW]  96.3 18.22 0 bottom
CC150  -  [C_0402NEW]  96.3 16.44 0 bottom
CC156  -  [C_0402NEW]  109.59 80.69 0 top
CC161  -  [C_0603NEW]  119.88 50.48 90 top
CC162  -  [C_0603NEW]  119.88 49.46 270 top
CC163  -  [C_0603NEW]  118.67 50.48 90 top
CC164  -  [C_0603NEW]  118.67 49.46 270 top
CC165  -  [C_0603NEW]  118.67 52.89 90 top
CC166  -  [C_0603NEW]  118.67 55.24 90 top
CC167  -  [C_D3]  91.5 48.47 180 top
CC168  -  [C_0603NEW]  127.56 42.03 0 top
CC169  -  [C_0603NEW]  123.89 44.52 90 top
CC170  -  [C_0603NEW]  125.15 42.03 0 top
CC171  -  [C_0603NEW]  125.6 44.13 90 top
CC172  -  [C_D2]  135.06 18.44 180 bottom
CC174  -  [C_0402NEW]  105.85 33.76 90 bottom
CC175  -  [C_0402NEW]  104.89 33.76 90 bottom
CC176  -  [C_D2]  104.15 17.23 0 bottom
CC177  -  [C_0402NEW]  137.75 23.03 0 top
CC178  -  [C_0402NEW]  96.3 17.33 0 bottom
CC179  -  [C_0402NEW]  96.3 19.11 0 bottom
CC180  -  [C_0603NEW]  119.88 55.24 90 top
CC181  -  [C_0603NEW]  119.88 52.89 90 top
CC183  -  [C_0603NEW]  127.93 44.13 90 top
CC250  -  [C_0402NEW]  115.73 50.96 270 top
CC251  -  [C_0402NEW]  110.75 50.7 270 top
CC252  -  [C_0402NEW]  112.59 47.5 180 top
CC253  -  [C_0402NEW]  115.05 52.24 90 top
CC254  -  [C_0402NEW]  117.09 49.39 90 top
CC255  -  [C_0402NEW]  111.66 55.3 0 top
CC256  -  [C_0402NEW]  117.09 52.94 90 top
CC257  -  [C_0402NEW]  115.75 49.16 270 top
CC258  -  [C_0402NEW]  117.09 51.16 90 top
CC259  -  [C_0402NEW]  114.36 55.3 180 top
CC260  -  [C_0402NEW]  123.87 46.86 90 top
CC261  -  [C_0402NEW]  125.47 46.59 90 top
CC262  -  [C_0402NEW]  127.12 46.59 90 top
CC263  -  [C_0402NEW]  122.9 47.6 90 top
CC264  -  [C_0402NEW]  129.29 46.62 0 top
CC573  -  [C_0402NEW]  117.1 47.63 90 top
CC574  -  [C_0402NEW]  117.12 55.25 180 top
CD1  -  [C_0402NEW]  69.36 12.75 180 bottom
CD2  -  [C_0402NEW]  69.36 13.7 180 bottom
CD3  -  [C_0402NEW]  76.42 62.84 90 top
CD4  -  [C_0402NEW]  76.51 46.76 180 top
CD5  -  [C_0402NEW]  68.13 46.13 270 top
CD6  -  [C_0402NEW]  73.07 62.85 90 top
CD7  -  [C_0402NEW]  66.57 12.75 0 bottom
CD8  -  [C_0402NEW]  66.57 13.7 0 bottom
CD9  -  [C_0603NEW]  76.36 56.3 270 top
CD10  -  [C_0603NEW]  76.36 58.3 90 top
CD11  -  [C_0603NEW]  76.29 49.16 90 top
CD12  -  [C_0603NEW]  68.13 59.51 270 top
CD13  -  [C_0603NEW]  68.17 48.68 270 top
CD14  -  [C_0603NEW]  68.06 55.76 270 top
CD15  -  [C_0603NEW]  68.18 61.38 90 top
CD16  -  [C_D3]  87.18 43.8 270 top
CD17  -  [C_0402NEW]  67.62 83.08 270 top
CD18  -  [C_0402NEW]  68.57 83.08 270 top
CD19  -  [C_0402NEW]  75.49 85.15 270 top
CD20  -  [C_0402NEW]  76.45 85.15 270 top
CD21  -  [C_0402NEW]  67.62 84.92 270 top
CD22  -  [C_0402NEW]  68.57 84.92 270 top
CD23  -  [C_0402NEW]  55.8 13.14 0 bottom
CD24  -  [C_0402NEW]  55.8 12.25 0 bottom
CD25  -  [C_0402NEW]  63.59 43.95 270 top
CD26  -  [C_0402NEW]  55.28 42.94 90 top
CD27  -  [C_0402NEW]  64.1 59 90 top
CD28  -  [C_0402NEW]  55.23 58.65 90 top
CD29  -  [C_0402NEW]  58.55 13.14 180 bottom
CD30  -  [C_0402NEW]  58.55 12.25 180 bottom
CD31  -  [C_0603NEW]  63.59 46.44 270 top
CD32  -  [C_0603NEW]  63.53 56.57 270 top
CD33  -  [C_0603NEW]  55.28 56.51 270 top
CD34  -  [C_0603NEW]  55.28 51.78 90 top
CD35  -  [C_0603NEW]  55.34 46.31 90 top
CD36  -  [C_0603NEW]  63.02 58.47 90 top
CD37  -  [C_0603NEW]  63.53 52.41 90 top
CD38  -  [C_D3]  82.42 43.8 270 top
CD39  -  [C_0402NEW]  63.98 83.4 270 top
CD40  -  [C_0402NEW]  63.09 83.4 270 top
CD41  -  [C_0402NEW]  55.78 81.98 270 top
CD42  -  [C_0402NEW]  54.89 81.98 270 top
CD43  -  [C_0402NEW]  54.89 80.2 270 top
CD44  -  [C_0402NEW]  55.78 80.2 270 top
CE3  -  [C_0402NEW]  270.4 52.28 0 bottom
CE4  -  [C_0402NEW]  256.23 54.61 180 bottom
CE757  -  [C_0402NEW]  290.1 11.86 180 top
CH1  -  [C_0402NEW]  122.38 21.55 0 top
CH2  -  [C_0402NEW]  176.14 28.23 90 bottom
CH3  -  [C_0402NEW]  177.03 26.45 90 bottom
CH4  -  [C_0402NEW]  187.53 37.85 0 bottom
CH5  -  [C_0402NEW]  187.6 41.47 0 bottom
CH6  -  [C_0402NEW]  120.6 21.55 0 top
CH18  -  [C_0402NEW]  163.67 47.33 180 bottom
CH19  -  [C_0402NEW]  160.98 47.33 0 bottom
CH30  -  [C_0603NEW]  157.15 33.65 0 top
CH31  -  [C_0402NEW]  160.22 28.9 90 top
CH32  -  [C_0402NEW]  157.02 31.17 0 top
CH33  -  [C_0402NEW]  154.93 33.68 180 top
CH34  -  [C_0402NEW]  175.76 43.63 270 bottom
CH35  -  [C_0402NEW]  174.79 43.63 270 bottom
CH36  -  [C_0805NEW]  177.28 44.43 270 bottom
CH43  -  [C_0402NEW]  180.07 43.02 90 bottom
CH44  -  [C_0603NEW]  147.25 32.7 90 top
CH45  -  [C_0402NEW]  157.05 29.55 0 top
CH46  -  [C_0402NEW]  154.93 32.13 180 top
CH47  -  [C_0402NEW]  157.02 32.13 0 top
CH48  -  [C_0402NEW]  158.74 27.19 90 top
CH49  -  [C_0402NEW]  153.36 29.56 90 top
CH50  -  [C_0402NEW]  162.02 32.12 180 top
CH51  -  [C_0402NEW]  144.8 31.87 270 top
CH52  -  [C_0402NEW]  141.19 34.15 180 bottom
CH53  -  [C_0402NEW]  144.85 27.47 90 top
CH54  -  [C_0402NEW]  160.56 15.75 270 bottom
CH55  -  [C_0402NEW]  162.5 25.88 270 top
CH56  -  [C_0402NEW]  158.83 29.5 90 top
CH59  -  [C_0402NEW]  163.85 27.94 0 top
CH60  -  [C_0402NEW]  164.36 32.62 0 top
CH63  -  [C_0402NEW]  184.16 36.54 270 bottom
CH64  -  [C_0805NEW]  181.6 28.43 270 bottom
CH65  -  [C_0805NEW]  183.41 28.43 270 bottom
CH66  -  [C_0402NEW]  161.92 28.84 270 top
CH67  -  [C_0402NEW]  160.41 33.71 180 top
CH68  -  [C_0402NEW]  163.42 27.07 270 top
CH69  -  [C_0402NEW]  159.83 32.13 180 top
CH70  -  [C_0603NEW]  164.65 29.46 0 top
CH71  -  [C_0603NEW]  182.49 34.1 90 bottom
CH72  -  [C_0402NEW]  156.66 15.75 270 bottom
CH73  -  [C_0603NEW]  174.62 41.56 0 bottom
CH74  -  [C_0402NEW]  162.78 36.87 270 top
CH75  -  [C_0402NEW]  162.54 34.48 0 top
CH76  -  [C_0402NEW]  161.3 36.51 180 top
CH77  -  [C_0402NEW]  159.61 27.18 0 top
CH78  -  [C_0402NEW]  164.71 26.14 90 top
CH79  -  [C_0402NEW]  159.4 25.23 270 top
CH81  -  [C_0402NEW]  157.74 35.17 180 top
CH82  -  [C_0402NEW]  156.15 29.78 90 top
CH84  -  [C_0402NEW]  161.42 25.78 180 top
CH85  -  [C_0603NEW]  143.06 18.79 180 bottom
CH86  -  [C_0402NEW]  142.51 20.86 180 bottom
CH87  -  [C_0402NEW]  142.51 19.97 180 bottom
CH88  -  [C_0402NEW]  170.05 29.51 90 top
CH89  -  [C_0402NEW]  170.93 29.51 90 top
CH90  -  [C_0402NEW]  170.05 28.65 270 top
CH91  -  [C_0402NEW]  154.72 30.06 270 top
CH92  -  [C_0402NEW]  138.91 35 90 bottom
CH93  -  [C_0402NEW]  142.3 40.37 0 bottom
CH94  -  [C_B2]  138.14 32.7 90 bottom
CH95  -  [C_B2]  140.64 38.3 180 bottom
CH96  -  [C_0402NEW]  156.72 36.75 90 top
CH97  -  [C_0402NEW]  140.33 22.72 270 bottom
CH98  -  [C_0402NEW]  192.17 22.48 0 bottom
CH101  -  [C_0402NEW]  178.88 33.14 180 bottom
CH102  -  [C_0402NEW]  161.36 35.17 180 top
CH103  -  [C_0402NEW]  153.76 35.96 270 top
CH104  -  [C_0402NEW]  153.76 36.81 90 top
CH105  -  [C_0805NEW]  143.41 35.79 180 bottom
CH106  -  [C_0603NEW]  163.3 30.45 180 top
CH107  -  [C_0402NEW]  190.23 23.2 180 bottom
CH109  -  [C_0402NEW]  171.61 45.73 90 top
CH110  -  [C_0402NEW]  169.79 48.05 90 bottom
CH111  -  [C_0402NEW]  166.86 42.49 270 top
CH112  -  [C_0402NEW]  169.79 48.05 90 top
CMOS1  -  [SHORTPADS]  192.04 32.43 270 bottom
D2  -  [RB751S40T1_SOD523-2]  167.73 101.13 0 bottom
D6  -  [BAT54CW_SOT323-3]  139.5 97.24 270 bottom
D9  -  [PESD5V0U2BT_SOT23-3]  83.7 96.8 180 bottom
D23  -  [PESD24VS2UT_SOT23-3]  166.93 54.12 270 bottom
D31  -  [RB751S40T1_SOD523-2]  254.93 68.2 270 top
D37  -  [PESD5V0U2BT_SOT23-3]  217.79 30.41 180 top
D59  -  [RB751V40_SC76-2]  170.99 70.63 180 bottom
D62  -  [RB751V40_SC76-2]  170.99 72.35 180 bottom
D65  -  [RB751V40_SC76-2]  90.01 65.99 270 top
D66  -  [RB751V40_SC76-2]  101.06 87.62 270 top
D67  -  [RB751V40_SC76-2]  98.01 87.62 270 top
D68  -  [RB751V40_SC76-2]  102.71 87.62 270 top
D69  -  [RB751V40_SC76-2]  96.36 87.62 270 top
D72  -  [PESD5V0U2BT_SOT23-3]  313.71 62.1 270 bottom
D73  -  [PESD5V0U2BT_SOT23-3]  204.54 12.02 90 bottom
D77  -  [PESD5V0U2BT_SOT23-3]  28.03 78.1 0 top
D78  -  [IP4292CZ10-TB_XSON10U10]  313.47 58.78 270 bottom
D81  -  [AZ5125-02SPR7G_SOT23-3]  15.27 33.33 90 bottom
D82  -  [AZ5125-02SPR7G_SOT23-3]  15.27 37.4 90 bottom
D83  -  [PESD5V0U2BT_SOT23-3]  12.76 67.08 90 top
D87  -  [PESD5V0U2BT_SOT23-3]  247.11 93.59 90 bottom
D88  -  [IP4292CZ10-TB_XSON10U10]  256.72 93.92 180 bottom
D89  -  [IP4292CZ10-TB_XSON10U10]  21.05 51.35 270 bottom
D90  -  [PESD5V0U2BT_SOT23-3]  20.59 46.48 270 bottom
D91  -  [RB751S40T1_SOD523-2]  271.88 45.81 180 bottom
D92  -  [RB751S40T1_SOD523-2]  254.93 63.97 270 top
D93  -  [RB751S40T1_SOD523-2]  254.93 61.31 270 top
D94  -  [RB751S40T1_SOD523-2]  270.54 64.55 0 top
DE1  -  [AZ5125-02SPR7G_SOT23-3]  245.01 63.8 180 top
DE2  -  [AZ5125-02SPR7G_SOT23-3]  249.08 63.8 180 top
DH2  -  [RB751V40_SC76-2]  182.81 36.93 90 bottom
DH3  -  [RB751V40_SC76-2]  184.08 34.37 270 bottom
FD1  -  [FIDUCIAL_C40M80]  46.67 9.71 180 bottom
FD2  -  [FIDUCIAL_C40M80]  313.73 93.65 180 bottom
FD3  -  [FIDUCIAL_C40M80]  38.44 9.03 0 top
FD4  -  [FIDUCIAL_C40M80]  313.73 93.65 0 top
H1  -  [H_2P8]  272 109.9 0 top
H2  -  [H_2P8]  62.6 109.9 0 top
H3  -  [H_2P8]  10.5 87.15 0 top
H4  -  [H_2P3]  22 3.9 0 top
H5  -  [H_2P8]  108.4 5.9 0 top
H6  -  [H_2P3]  324.5 93.4 0 top
H7  -  [H_2P8]  267.5 6.9 0 top
H8  -  [H_2P3]  323.5 36.75 0 top
H9  -  [H_2P8]  196 3.9 0 top
H10  -  [H_2P8]  139 107.9 0 top
H11  -  [H_5P4N]  175.53 54.65 0 top
H12  -  [H_2P0]  323.5 42.25 0 top
H13  -  [H_3P2]  275.9 86.8 0 top
H14  -  [H_3P2]  241.9 86.8 0 top
H16  -  [H_3P2]  216.25 42 0 top
H17  -  [H_3P2]  200.85 40.9 0 top
H19  -  [H_3P8]  108.23 26.15 0 top
H20  -  [H_3P8]  132.73 75.65 0 top
H21  -  [H_3P8]  132.73 26.15 0 top
H22  -  [H_3P8]  108.23 75.65 0 top
H23  -  [H_2P8X2P3]  22 9.4 180 top
H24  -  [H_2P5X2P0]  144.5 107.9 0 top
H26  -  [H_2P3]  4.65 61.4 0 top
JBT1  -  [ACES_50224-0120N-001_12P]  316.43 16.4 90 top
JCAP2  -  [ACES_50506-00841-P01_8P-T]  145.2 54.99 180 top
JCRT1  -  [TYCO_2041127-1_15P]  6.1 70.82 90 bottom
JDEG2  -  [HB_A531015-SCHR21_10P]  260.45 58.8 0 top
JDIMM1  -  [TYCO_2-2013022-1_204P]  68.2 22.25 270 bottom
JDIMM2  -  [TYCO_2-2013287-1_204P]  55.2 19.25 270 bottom
JESA1  -  [TAIWI_EU147-167CRL-TWD_16P]  259.5 99.27 0 bottom
JFAN1  -  [ACES_50271-0040N-001_4P]  159.12 96.43 180 bottom
JFP1  -  [ACES_50505-00641-001_6P-T]  232.95 25 0 top
JHDMI1  -  [HONGL_13-13201904CP_19P]  71.5 103.97 0 bottom
JHP1  -  [SINGA_2SJ3053-100111F_6P-T]  11.5 28.15 270 bottom
JLED1  -  [ACES_50506-00841-P01_8P-T]  165.75 62 180 top
JLID1  -  [HB_A080415-SAHR21_4P-T]  28.5 12.63 0 top
JLOM1  -  [SANTA_130456-241_13P-T]  317.76 82.47 270 bottom
JLVDS1  -  [STARC_107K40-000001-G2_40P]  111.1 109.25 180 bottom
JLVDS2  -  [E-T_3703K-F12N-03R_12P]  129.91 107.46 180 bottom
JMINI1  -  [LCN_DAN08-52406-0500_52P]  299.8 34.55 180 bottom
JMINI2  -  [LCN_DAN08-52406-0500_52P]  265.8 58.7 180 bottom
JMINI3  -  [LCN_DAN08-52406-0500_52P]  268.5 41.7 270 bottom
JRTC1  -  [ACES_50271-0020N-001_2P]  317.38 10.2 0 top
JSC1  -  [HB_A081015-SAHR21_10P-T]  78.82 11.38 0 top
JSD1  -  [T-SOL_156-4000000606_15P-T]  295.03 4.85 270 bottom
JSIM1  -  [HB_5620821-SICR11_9P]  287.78 26.35 180 bottom
JSNIF1  -  [ACES_50504-0040N-001_4P]  14.5 2.56 180 top
JSPK1  -  [ACES_50269-00401-001_4P-T]  249.8 67.53 180 top
JTAA1  -  [ACES_50169-01441-001_14P-T]  203.55 24 90 bottom
JTAG1  -  [SHORTPADS]  284.09 45.4 270 top
JTP1  -  [ACES_50506-01641-P01_16P-T]  216.55 24.8 0 top
JUSB1  -  [SANTA_373070-1_9P-T]  316.69 54.4 270 bottom
JUSB3  -  [SANTA_373070-1_9P-T]  15.31 53 90 bottom
JXDP1  -  [MOLEX_52435-2671_26P-T]  89.13 83.28 270 top
JXDP2  -  [MOLEX_52435-2671_26P-T]  113.92 20.04 0 top
L10  -  [MURAT_DLW21SN121SQ2L_4P]  102.74 88.77 180 bottom
L19  -  [MURAT_DLW21SN900HQ2L_0805_4P-S]  72.32 97.27 90 bottom
L20  -  [MURAT_DLW21SN900HQ2L_0805_4P-S]  76.21 97.27 90 bottom
L21  -  [MURAT_DLW21SN900HQ2L_0805_4P-S]  67.04 96.89 90 bottom
L22  -  [MURAT_DLW21SN900HQ2L_0805_4P-S]  64.89 96.9 90 bottom
L29  -  [TAIYO_CBC2012T4R7M_2P]  295.83 81.19 90 top
L44  -  [MURAT_BLM18BD601SN1D_2P]  275.15 19.81 270 top
L45  -  [MURAT_BLM18PG471SN1D_2P]  289.43 7.71 180 top
L47  -  [MURAT_BLM18BD601SN1D_2P]  276.04 7.53 90 top
L51  -  [MURAT_DLW21SN900SQ2L_0805_4P]  308.01 62.44 0 bottom
L52  -  [MURAT_DLW21SN900SQ2L_0805_4P-S]  200.44 13.41 0 bottom
L54  -  [MURAT_BLM15AG601SN1D_2P]  225.65 30.08 180 top
L55  -  [MURAT_BLM15AG601SN1D_2P]  221.63 30.08 0 top
L77  -  [MURAT_BLM21PG600SN1D_L0805_2P]  21.81 29.41 270 top
L91  -  [MURAT_BLM18PG121SN1D_2P]  250.63 56.8 90 top
L92  -  [MURAT_BLM18PG121SN1D_2P]  248.21 56.75 90 top
L93  -  [MURAT_BLM18PG121SN1D_2P]  244.72 56.75 90 top
L94  -  [MURAT_BLM18PG121SN1D_2P]  243.35 56.75 90 top
L95  -  [MURAT_DLW21SN900HQ2L_0805_4P]  309.09 59.14 0 bottom
L96  -  [MURAT_DLW21SN900HQ2L_0805_4P]  309.09 57.3 0 bottom
L99  -  [MURAT_BLM15AG121SN1D_2P]  10.41 68.99 90 bottom
L100  -  [MURAT_BLM15AG121SN1D_2P]  11.36 71.21 90 bottom
L101  -  [MURAT_BLM15AG121SN1D_2P]  11.36 74.93 90 bottom
L102  -  [MURAT_BLM15AG121SN1D_2P]  12.93 74.93 90 top
L103  -  [MURAT_BLM15AG121SN1D_2P]  10.93 79.81 270 top
L104  -  [MURAT_BLM18BD601SN1D_2P]  20.27 36.47 0 bottom
L105  -  [MURAT_BLM18BD601SN1D_2P]  20.38 31.6 90 bottom
L106  -  [MURAT_BLM18BD601SN1D_2P]  20.38 34.02 90 bottom
L110  -  [MURAT_DLW21SN900HQ2L_0805_4P]  259.65 92.08 180 bottom
L111  -  [MURAT_DLW21SN900SQ2L_0805_4P]  251.15 90.86 90 bottom
L112  -  [MURAT_DLW21SN900HQ2L_0805_4P]  254.58 90.86 90 bottom
L113  -  [MURAT_DLW21SN900SQ2L_0805_4P]  24.28 47.15 180 bottom
L114  -  [MURAT_DLW21SN900HQ2L_0805_4P]  24.28 48.99 180 bottom
L115  -  [MURAT_DLW21SN900HQ2L_0805_4P]  24.28 50.83 180 bottom
L116  -  [DELTA_0402HS-9N0EJTS_2P]  73.27 97.64 90 bottom
L117  -  [DELTA_0402HS-9N0EJTS_2P]  72.21 97.64 90 bottom
L118  -  [DELTA_0402HS-9N0EJTS_2P]  77.17 97.62 90 bottom
L119  -  [DELTA_0402HS-9N0EJTS_2P]  76.1 97.62 90 bottom
L120  -  [DELTA_0402HS-9N0EJTS_2P]  67.99 97.31 90 bottom
L121  -  [DELTA_0402HS-9N0EJTS_2P]  66.92 97.31 90 bottom
L122  -  [DELTA_0402HS-9N0EJTS_2P]  65.86 97.31 90 bottom
L123  -  [DELTA_0402HS-9N0EJTS_2P]  64.79 97.31 90 bottom
L124  -  [DELTA_0603CS-120EJTS_2P]  298 87.2 0 top
L125  -  [DELTA_0603CS-120EJTS_2P]  297.99 85.71 0 top
L126  -  [DELTA_0603CS-120EJTS_2P]  297.99 84.21 0 top
L127  -  [DELTA_0603CS-120EJTS_2P]  297.99 82.74 0 top
L128  -  [DELTA_0603CS-120EJTS_2P]  297.52 80.92 0 top
L129  -  [DELTA_0603CS-120EJTS_2P]  297.52 79.42 0 top
L130  -  [DELTA_0603CS-120EJTS_2P]  297.52 77.93 0 top
L131  -  [DELTA_0603CS-120EJTS_2P]  297.52 76.44 0 top
LE3  -  [MURAT_BLM15BB221SN1D_2P]  37.71 33.72 0 top
LE92  -  [MURAT_BLM15BB221SN1D_2P]  99.82 89.24 0 top
LH1  -  [TDK_GLFR1608T1R0M-LR_2P]  178.88 43.04 90 bottom
LH6  -  [TAIYO_LBR2012T100M_2P]  137.51 36.46 270 bottom
LH7  -  [TAIYO_LBR2012T100M_2P]  137.14 38.19 0 bottom
LH8  -  [TDK_MLG1608BR10JT_2P]  142.33 34.17 0 bottom
ME1  -  [SHORTPADS]  193.45 37.6 90 bottom
NOREF  -  []  108.23 75.65 0 top
NOREF#2  -  []  132.72 75.65 0 top
NOREF#3  -  []  200.85 40.9 0 top
NOREF#4  -  []  109.64 151.11 0 top
NOREF#5  -  []  216.25 42 0 top
NOREF#6  -  []  323.5 42.25 0 top
NOREF#7  -  []  275.9 86.8 0 top
NOREF#8  -  []  105.54 43.5 90 top
NOREF#9  -  []  294.35 7.9 90 top
NOREF#10  -  []  115.74 110.18 90 top
NOREF#11  -  []  62.6 109.9 0 top
NOREF#12  -  []  323.5 42.25 0 top
NOREF#13  -  []  132.72 26.15 0 top
NOREF#14  -  []  108.4 5.9 180 top
NOREF#15  -  []  267.5 6.9 0 top
NOREF#16  -  []  4.65 61.4 0 top
NOREF#17  -  []  10.5 87.15 0 top
NOREF#18  -  []  83.72 14.69 90 top
NOREF#19  -  []  324.5 93.4 0 top
NOREF#20  -  []  90.44 22.18 90 top
NOREF#21  -  []  272 109.9 90 top
NOREF#22  -  []  108.23 26.15 0 top
NOREF#23  -  []  196 3.9 180 top
NOREF#24  -  []  241.9 86.8 0 top
NOREF#25  -  []  175.52 54.65 0 top
NOREF#26  -  []  179.96 -58.38 0 top
NOREF#27  -  []  95.47 84.41 270 bottom
NOREF#28  -  []  93.67 44.35 270 bottom
NOREF#29  -  []  88.36 70.63 270 bottom
PBATT1  -  [SUYIN_200277MR009F515ZR_7P]  59 2.25 180 bottom
PC3  -  [C_0603NEW]  312.83 7.64 270 top
PC4  -  [C_0402NEW]  57.24 7.5 90 bottom
PC5  -  [C_0402NEW]  56.29 7.5 90 bottom
PC8  -  [C_0402NEW]  41.69 74.52 90 top
PC9  -  [C_0603NEW]  36.73 72.03 90 top
PC10  -  [C_0805NEW]  15.13 67.9 0 bottom
PC11  -  [C_0402NEW]  14.15 62.76 180 top
PC12  -  [C_0402NEW]  24.59 68.22 0 top
PC13  -  [C_0402NEW]  14.15 63.78 180 top
PC14  -  [C_0402NEW]  14.15 61.74 180 top
PC15  -  [C_0805NEW]  14.15 60.14 180 bottom
PC16  -  [C_0402NEW]  16.49 65.75 180 top
PC17  -  [C_0402NEW]  32.47 75.52 0 top
PC18  -  [C_0402NEW]  19.22 75.41 0 top
PC74  -  [C_0603NEW]  145.26 13.99 90 bottom
PC75  -  [C_0603NEW]  146.46 15.39 270 bottom
PC76  -  [C_0402NEW]  138.6 12.28 180 bottom
PC77  -  [C_0402NEW]  137.37 3.69 180 bottom
PC78  -  [C_0402NEW]  141.38 14.42 90 bottom
PC80  -  [C_0402NEW]  135.57 11.8 0 bottom
PC81  -  [C_0805NEW]  129.89 6.68 90 bottom
PC82  -  [C_0805NEW]  127.92 6.68 90 bottom
PC83  -  [C_0402NEW]  128.67 11.49 180 bottom
PC84  -  [C_0805NEW]  127.84 15.14 0 bottom
PC85  -  [C_0805NEW]  127.84 12.91 0 bottom
PC86  -  [C_0402NEW]  147.94 2.75 90 bottom
PC87  -  [C_0402NEW]  149.33 3.64 270 bottom
PC88  -  [C_0805NEW]  148.39 8.63 90 bottom
PC89  -  [C_0805NEW]  150.25 8.66 90 bottom
PC90  -  [C_0402NEW]  145.81 3.83 0 bottom
PC91  -  [C_0402NEW]  145.81 2.82 0 bottom
PC92  -  [C_0402NEW]  143.99 2.87 90 bottom
PC100  -  [C_0402NEW]  258.84 16.51 180 top
PC101  -  [C_0603NEW]  249.07 6.87 90 bottom
PC102  -  [C_0402NEW]  262.4 13.17 0 top
PC103  -  [C_0805NEW]  262.01 14.63 0 top
PC104  -  [C_0402NEW]  242.14 8.8 0 bottom
PC105  -  [C_0402NEW]  242.14 9.74 0 bottom
PC106  -  [C_0805NEW]  239.92 13.33 180 bottom
PC107  -  [C_0603NEW]  251.29 6.87 90 bottom
PC108  -  [C_0402NEW]  254.01 10.4 270 top
PC109  -  [C_0402NEW]  243.81 9.03 90 top
PC110  -  [C_B2]  260.78 12.79 0 bottom
PC111  -  [C_B2]  225.55 3.57 180 bottom
PC112  -  [C_0402NEW]  253.57 13.9 0 bottom
PC113  -  [C_0402NEW]  232.71 13.92 0 bottom
PC114  -  [C_0805NEW]  247.11 14.23 90 top
PC115  -  [C_0603NEW]  250.98 15.14 90 top
PC116  -  [C_0402NEW]  248.51 14.74 90 top
PC117  -  [C_0603NEW]  248.82 18.95 270 top
PC118  -  [C_0805NEW]  239.92 11.48 180 bottom
PC119  -  [C_0805NEW]  259.25 14.63 180 top
PC120  -  [C_0402NEW]  252.08 5.29 270 bottom
PC121  -  [C_0402NEW]  248.27 4.38 90 bottom
PC215  -  [C_0402NEW]  40.47 60.47 0 top
PC253  -  [C_0603NEW]  40.86 68.41 90 top
PC255  -  [C_0402NEW]  41.99 66.13 0 top
PC263  -  [C_0603NEW]  34.8 63.23 180 top
PC265  -  [C_B2]  23.95 55.01 0 bottom
PC272  -  [C_0603NEW]  39.65 69.81 270 top
PC274  -  [C_0805NEW]  29.05 60.03 0 top
PC275  -  [C_0402NEW]  26.42 68.23 0 top
PC276  -  [C_0805NEW]  29.05 58.19 0 top
PC277  -  [C_0402NEW]  39.2 61.17 180 top
PC278  -  [C_0402NEW]  34.96 66.79 180 top
PC279  -  [C_0402NEW]  29.16 62.44 0 top
PC280  -  [C_0603NEW]  34.8 61.96 180 top
PC281  -  [C_0402NEW]  29.16 61.43 0 top
PC282  -  [C_0402NEW]  40.47 59.59 0 top
PC300  -  [C_0805NEW]  95.43 8.81 0 bottom
PC301  -  [C_0402NEW]  95.51 2.38 180 bottom
PC302  -  [C_0805NEW]  101.94 9.52 180 bottom
PC303  -  [C_0805NEW]  103.71 10.58 0 bottom
PC304  -  [C_0402NEW]  98.11 3.29 270 bottom
PC305  -  [C_0402NEW]  102.43 2.52 0 bottom
PC306  -  [C_0402NEW]  101.61 8.13 180 bottom
PC307  -  [C_0402NEW]  93.38 8.96 180 bottom
PC400  -  [C_0805NEW]  153.46 61.3 180 top
PC401  -  [C_0402NEW]  153.71 64.14 180 top
PC402  -  [C_0402NEW]  153.71 63.19 180 top
PC403  -  [C_0805NEW]  153.46 59.4 180 top
PC404  -  [C_0402NEW]  155.34 61.36 0 bottom
PC405  -  [C_0402NEW]  157.13 63.79 0 top
PC406  -  [C_B2]  159.62 54.29 180 bottom
PC407  -  [C_0402NEW]  158.11 70.7 180 bottom
PC408  -  [C_0402NEW]  159.62 56.63 180 bottom
PC500  -  [C_0805NEW]  124.94 4.21 270 top
PC501  -  [C_0402NEW]  122.65 3.97 270 top
PC502  -  [C_0402NEW]  121.76 3.97 270 top
PC503  -  [C_0805NEW]  126.95 4.21 270 top
PC504  -  [C_0402NEW]  120.05 10.23 90 top
PC505  -  [C_0603NEW]  119.98 12.21 180 top
PC506  -  [C_0402NEW]  126.22 10.44 180 bottom
PC508  -  [C_0402NEW]  124.06 2.51 180 bottom
PC510  -  [C_0402NEW]  130.47 12.79 180 top
PC511  -  [C_B2]  112.21 12.09 0 bottom
PC701  -  [C_0402NEW]  137.64 87.26 90 top
PC702  -  [C_0402NEW]  136.78 88.19 90 bottom
PC703  -  [C_0402NEW]  136.75 88.17 270 top
PC704  -  [C_0402NEW]  136.75 92.17 270 bottom
PC705  -  [C_0402NEW]  137.75 87.18 180 bottom
PC706  -  [C_0402NEW]  142.54 86.19 180 top
PC707  -  [C_0402NEW]  140.25 91.2 270 bottom
PC708  -  [C_0402NEW]  141.18 91.2 270 bottom
PC709  -  [C_0402NEW]  142.12 93.57 270 bottom
PC710  -  [C_0402NEW]  140.7 88.48 0 bottom
PC711  -  [C_0402NEW]  138.84 88.47 90 bottom
PC714  -  [C_0603NEW]  144.33 81.53 90 top
PC715  -  [C_0603NEW]  143.06 81.53 90 top
PC719  -  [C_0402NEW]  148.24 86.9 270 top
PC722  -  [C_0402NEW]  151.34 82.7 0 bottom
PC723  -  [C_0402NEW]  148.68 82.75 90 bottom
PC727  -  [C_0402NEW]  149.56 82.7 0 bottom
PC729  -  [C_0402NEW]  151.36 82.74 270 top
PC732  -  [C_B2]  153.22 67.91 90 bottom
PC733  -  [C_0805NEW]  150.65 75.64 90 bottom
PC734  -  [C_0805NEW]  152.49 75.64 90 bottom
PC736  -  [C_0402NEW]  149.28 76.16 90 bottom
PC737  -  [C_0402NEW]  152.35 84.48 0 bottom
PC738  -  [C_0402NEW]  149.07 87.35 270 bottom
PC739  -  [C_0402NEW]  151.62 89.13 270 bottom
PC740  -  [C_0402NEW]  153.43 89.77 270 bottom
PC741  -  [C_0402NEW]  148.67 84.54 0 bottom
PC742  -  [C_0402NEW]  147.24 79.4 180 bottom
PC743  -  [C_0402NEW]  152.75 87.35 270 bottom
PC744  -  [C_0402NEW]  151.86 87.35 270 bottom
PC745  -  [C_0402NEW]  141.76 73.35 90 bottom
PC746  -  [C_0805NEW]  132.24 87.21 0 top
PC747  -  [C_0805NEW]  132.24 89.05 0 top
PC748  -  [C_0805NEW]  132.24 83.55 0 top
PC749  -  [C_0402NEW]  132.64 85.79 0 top
PC750  -  [C_0402NEW]  139.03 82.31 90 bottom
PC751  -  [C_0402NEW]  125.61 85.32 0 bottom
PC752  -  [C_0402NEW]  132.64 84.9 0 top
PC753  -  [C_D]  158.57 73.72 90 bottom
PC754  -  [C_0402NEW]  153.84 76.03 90 bottom
PC1111  -  [C_0805NEW]  123.72 69.49 0 top
PC1112  -  [C_0805NEW]  120.29 71.71 0 bottom
PC1113  -  [C_0805NEW]  126.55 82.67 0 top
PC1114  -  [C_0805NEW]  127.65 71.84 0 bottom
PC1115  -  [C_0805NEW]  120.29 69.87 0 bottom
PC1116  -  [C_0805NEW]  123.59 69.87 0 bottom
PC1117  -  [C_0805NEW]  127.65 69.94 0 bottom
PC1118  -  [C_0805NEW]  123.59 71.71 0 bottom
PC1119  -  [C_0805NEW]  139.79 49.16 90 top
PC1120  -  [C_0805NEW]  139.79 46.15 90 top
PC1121  -  [C_0805NEW]  139.79 60.87 270 bottom
PC1122  -  [C_0805NEW]  139.79 52.19 90 top
PC1123  -  [C_0805NEW]  137.47 53.22 270 bottom
PC1124  -  [C_0805NEW]  115.91 36.73 0 top
PC1125  -  [C_0805NEW]  116.72 25.14 0 bottom
PC1126  -  [C_0805NEW]  139.86 57.06 270 bottom
PC1127  -  [C_0805NEW]  139.82 49.41 270 bottom
PC1128  -  [C_0805NEW]  137.47 49.41 270 bottom
PC1129  -  [C_0805NEW]  139.82 53.22 270 bottom
PC1130  -  [C_0805NEW]  137.41 60.84 270 bottom
PC1131  -  [C_0805NEW]  137.47 57.03 270 bottom
PC1132  -  [C_0805NEW]  126.55 80.88 0 top
PC1133  -  [C_0805NEW]  112.55 80.35 90 top
PC1134  -  [C_0805NEW]  114.36 80.35 90 top
PC1135  -  [C_0805NEW]  120.22 69.49 0 top
PC1136  -  [C_0805NEW]  142.33 47.57 90 top
PC1137  -  [C_0402NEW]  124.12 59.81 0 top
PC1138  -  [C_0402NEW]  123.2 59.81 180 top
PC1139  -  [C_0402NEW]  121.35 58.48 180 top
PC1140  -  [C_0402NEW]  124.66 65.46 180 top
PC1141  -  [C_0402NEW]  121.1 66.99 180 top
PC1142  -  [C_0402NEW]  122.22 58.48 0 top
PC1147  -  [C_0402NEW]  121.29 59.81 180 top
PC1148  -  [C_0402NEW]  121.96 65.46 0 top
PC1149  -  [C_0402NEW]  121.1 65.46 180 top
PC1150  -  [C_0402NEW]  123.2 61.15 180 top
PC1151  -  [C_0402NEW]  124.66 66.99 180 top
PC1154  -  [C_0805NEW]  120.08 25.14 0 bottom
PC1155  -  [C_0805NEW]  118.95 34.2 0 top
PC1156  -  [C_0805NEW]  122.48 34.17 0 top
PC1157  -  [C_D3]  123.68 82.14 180 top
PC1158  -  [C_D2]  119.35 80.39 180 bottom
PC1159  -  [C_0805NEW]  116.72 27.45 0 bottom
PC1160  -  [C_0805NEW]  120.02 27.45 0 bottom
PC1161  -  [C_0805NEW]  117.05 34.3 180 top
PC1162  -  [C_0805NEW]  123.3 25.14 0 bottom
PC1165  -  [C_SX]  119.2 18.44 0 bottom
PC1166  -  [C_SX]  119.2 13.55 0 bottom
PC1167  -  [C_0805NEW]  123.27 27.44 0 bottom
PC1168  -  [C_SX]  143.27 54.02 0 bottom
PC1169  -  [C_SX]  143.27 49.07 0 bottom
PC1170  -  [C_SX]  143.27 58.97 0 bottom
PC1172  -  [C_0402NEW]  117.63 61.92 90 top
PC1175  -  [C_0402NEW]  119.39 58.48 180 top
PC1176  -  [C_0402NEW]  121.98 47.6 90 top
PC1177  -  [C_0402NEW]  118.62 43.18 180 top
PC1178  -  [C_0402NEW]  110.9 44.85 0 top
PC1179  -  [C_0402NEW]  120.44 37.92 270 top
PC1180  -  [C_0402NEW]  116.92 41.36 180 top
PC1181  -  [C_0402NEW]  113.54 41.98 180 top
PC1182  -  [C_0402NEW]  118.9 40.24 270 top
PC1183  -  [C_0402NEW]  115.02 45.43 90 top
PC1184  -  [C_0402NEW]  122.87 42.67 90 top
PC1185  -  [C_0402NEW]  119.42 59.84 180 top
PC1186  -  [C_0402NEW]  119.58 43.18 0 top
PC1188  -  [C_0402NEW]  120.44 40.59 270 top
PC1189  -  [C_0402NEW]  116.41 46.82 270 top
